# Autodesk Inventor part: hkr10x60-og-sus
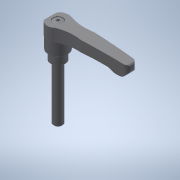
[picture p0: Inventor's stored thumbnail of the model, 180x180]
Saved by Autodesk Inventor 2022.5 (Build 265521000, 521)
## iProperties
Created: 2017-09
Part Number: hkr10x60-og-sus
Material: 一般
Document SubType Name: Modeling
Designer: imaocorp
Density: 1 g/cm^3
Appearance: 既定
Author: imaocorp
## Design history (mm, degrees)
node "hkr10x60-og-sus.x_t1"
node "hkr10x60-og-sus"
node "Base1"
